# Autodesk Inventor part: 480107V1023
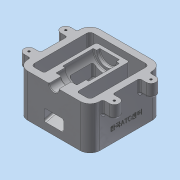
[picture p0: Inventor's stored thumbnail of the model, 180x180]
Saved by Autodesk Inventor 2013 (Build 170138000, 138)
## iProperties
Created: 2018-01
Part Number: 480107V1023
Material: 알루미늄 6061
Document SubType Name: Modeling
Designer: dgall
Density: 2.71 g/cm^3
Mass: 998.942 g
Surface Area: 834.93 cm^2
Volume: 368.613 cm^3
Author: dgall
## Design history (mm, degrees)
sketch "스케치1"
  geometry: L1 (-55, 55)-(55, 55); L2 (55, 55)-(55, -55); L3 (55, -55)-(-55, -55); L4 (-55, -55)-(-55, 55); 3 further points
  constraints: 8 end point, 2 midpoint, 2 parallel, 1 horizontal, 1 horizontal alignment, 1 perpendicular, 1 vertical alignment
  dimensions: "d0" = 110 distance of L2.end L3.end; "d1" = 110 distance of L1.end L2.end
extrude "돌출1" new body sketch "스케치1" distance "d2" = 65; taper "d3" = 0 deg
fillet "모깎기1" dims "d4" = 15
sketch "스케치2"
  geometry: L1 (-55, 40)-(-55, -40) reference; L2 (-40, -55)-(40, -55) reference; L3 (-65, -20.5)-(-21.874, -20.5); L4 (-21.874, -20.5)-(-21.874, -35.5); L5 (-21.874, -35.5)-(-65, -35.5); L6 (-65, -35.5)-(-65, -20.5); C1 r 7.5 at (-65, -28); C2 r 7.5 at (-65, 28); 2 further points
  constraints: 8 end point, 2 centre point, 2 parallel, 1 coincident, 1 horizontal, 1 midpoint, 1 perpendicular
  dimensions: "d5" = 15 diameter of C1; "d6" = 15 diameter of C2; "d7" = 27 distance from line of L2 C1.centre; "d8" = 56 distance of C2.centre C1.centre; "d9" = 10 distance from line of C1.centre L1; "d10" = 15 distance of L3.end L4.end
extrude "돌출2" join sketch "스케치2" distance "d11" = 20; taper "d12" = 0 deg
hole "구멍1" diameter "d15" = 3.242; stored, may be unused: countersink angle "d19" = 90 deg, drill point angle "d21" = 118 deg; dims "d13" = 10, "d14" = 10, "d16" = 9, "d17" = 4, "d18" = 2, "d20" = 11
hole "구멍2" diameter "d24" = 3.242; stored, may be unused: countersink angle "d28" = 90 deg, drill point angle "d30" = 118 deg; dims "d22" = 10, "d23" = 10, "d25" = 9, "d26" = 4, "d27" = 2, "d29" = 11
hole "구멍3" diameter "d33" = 3.242; stored, may be unused: countersink angle "d37" = 90 deg, drill point angle "d39" = 118 deg; dims "d31" = 10, "d32" = 10, "d34" = 9, "d35" = 4, "d36" = 2, "d38" = 11
hole "구멍4" diameter "d42" = 3.242; stored, may be unused: countersink angle "d46" = 90 deg, drill point angle "d48" = 118 deg; dims "d40" = 10, "d41" = 10, "d43" = 9, "d44" = 4, "d45" = 2, "d47" = 11
sketch "스케치3"
  geometry: L1 (40, 55)-(-40, 55) reference; L2 (55, -20.5)-(55, 20.5) reference; L3 (-45, 45)-(45, 45); L4 (45, 45)-(45, -45); L5 (45, -45)-(-45, -45); L6 (-45, -45)-(-45, 45); 3 further points
  constraints: 8 end point, 2 midpoint, 2 parallel, 1 horizontal, 1 horizontal alignment, 1 perpendicular, 1 vertical alignment
  dimensions: "d49" = 10 distance between parallel lines of L2 L4; "d50" = 10 distance between parallel lines of L1 L3
extrude "돌출3" cut sketch "스케치3" stored distance "d51" = 20; taper "d52" = 0 deg
fillet "모깎기2" dims "d53" = 5
sketch "스케치5"
  geometry: L1 (-45, 65)-(-45, 0) reference; L2 (-45, 65)-(35, 65); L3 (35, 65)-(35, 30); L4 (35, 30)-(-45, 8.564); L5 (-45, 65)-(-45, 8.564); L6 (55, 65)-(55, 0) reference; L7 (55, 0)-(40, 0) reference; 1 further point
  constraints: 8 end point, 2 perpendicular, 1 collinear, 1 point on line
  dimensions: "d56" = 20 distance between parallel lines of L6 L3; "d57" = 105 deg angle of L4 L1; "d58" = 30 distance from line of L7 L3.end
extrude "돌출4" join sketch "스케치5" stored distance "d59" = 50; taper "d60" = 0 deg
sketch "스케치6"
  geometry: L1 (-40, -55)-(40, -55) reference; L2 (0, -69.024)-(0, 40); L3 (0, -55)-(-7.5, -55); L4 (-7.5, -36)-(-7.5, -55); L5 (-7.5, -36)-(-16, -36); L6 (-16, -36)-(-16, -22); L7 (-16, -22)-(-20, -22); L8 (-20, -22)-(-20, 25); L9 (-20, 25)-(-15, 25); L10 (-15, 25)-(-15, 30); L11 (-15, 30)-(0, 30); 2 further points
  constraints: 20 end point, 5 perpendicular, 4 parallel, 3 point on line, 1 coincident, 1 midpoint, 1 vertical alignment
  dimensions: "d62" = 15 diameter of L4 L2; "d64" = 14 distance of L5.end L6.end; "d65" = 19 distance of L4.start L3.end; "d66" = 47 distance of L7.end L8.end; "d67" = 5 distance of L9.end L10.end; "d68" = 32 diameter of L6 L2; "d69" = 40 diameter of L8 L2; "d70" = 30 diameter of L10 L2
revolve "회전1" sketch "스케치6" stored, may be unused: angle "d71" = 90 deg
sketch "스케치7"
  geometry: L1 (35, 30)-(-45, 8.564) reference; L2 (20, 31.157)-(-55, 11.061); L3 (25, 65)-(25, 45) reference; L4 (-22, 65)-(-22, 45) reference; L5 (20, 56.157)-(20, 31.157); L6 (-17, 56.157)-(-17, 39.243); L7 (-55, 0)-(-55, 65) reference; L8 (-55, 11.061)-(-55, 29.061); L9 (-55, 29.061)-(-17, 39.243); L10 (25, 45)-(-22, 45) reference; L11 (-17, 56.157)-(20, 56.157); 1 further point
  constraints: 12 end point, 3 parallel, 2 point on line, 1 perpendicular
  dimensions: "d72" = 5 distance between parallel lines of L1 L2; "d73" = 5 distance between parallel lines of L3 L5; "d74" = 5 distance between parallel lines of L6 L4; "d75" = 18 distance of L2.end L8.end; "d76" = 105 deg angle of L8 L9; "d77" = 25 distance from line of L2.start L11
extrude "돌출5" cut sketch "스케치7" stored distance "d78" = 30; taper "d79" = 0 deg
fillet "모깎기3" dims "d80" = 3
fillet "모깎기4" dims "d81" = 3
fillet "모깎기5" dims "d82" = 3
fillet "모깎기6" dims "d83" = 3
chamfer "모따기1" distance "d84" = 1; stored, may be unused: second distance "d85" = 2, angle "d86" = 45 deg
chamfer "모따기2" distance "d87" = 1; stored, may be unused: second distance "d88" = 2, angle "d89" = 45 deg
fillet "모깎기7" dims "d90" = 1
fillet "모깎기8" dims "d91" = 3
fillet "모깎기9" dims "d92" = 3
node "작업 평면4"
sketch "스케치8"
  geometry: L1 (-55, 65)-(-55, 0) reference; L2 (55, 0)-(40, 0) reference; 2 further points
  constraints: 1 other
  dimensions: "d94" = 55 distance from line of point (0, 20) L1; "d95" = 20 distance from line of L2 point (0, 20)
feature "엠보싱1" sketch "스케치8" dims "d0" = 110, "d1" = 110, "d5" = 15, "d6" = 15, "d7" = 27, "d8" = 56, "d9" = 10, "d10" = 15, "d96" = 0.5, "d97" = 0
node "솔리드1"
mirror "대칭1"
mirror "대칭2"
node "작업 평면1"
node "작업 평면2"
node "작업 평면3"
other parameters: "d93" = 91.25
